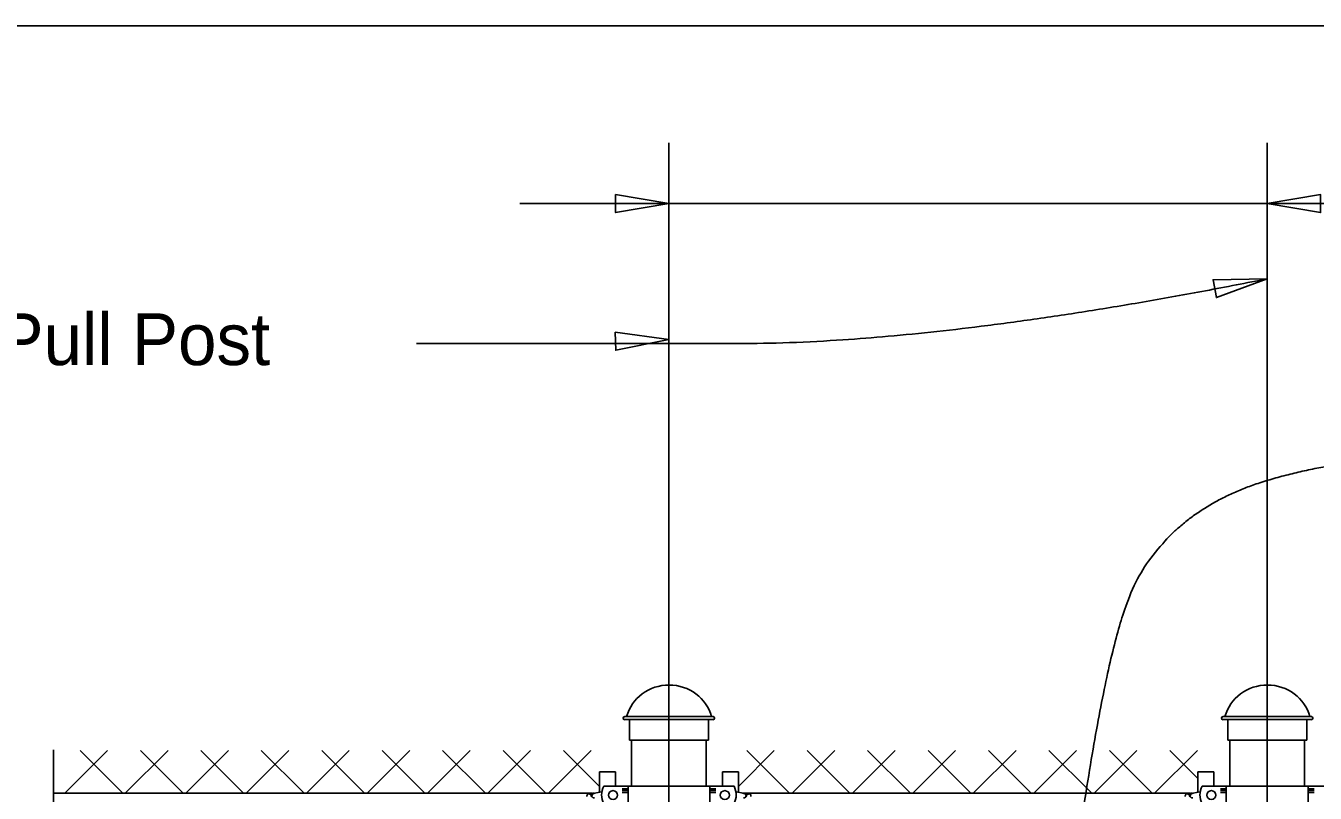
# Model space of a CAD drawing. Extents: x 0 to 72.1, y -7 to 30.
# Drawn here: x 23.75 to 28.78, y 25.02 to 28.01 of the extents above; entities that cross this region are included whole.
import ezdxf

# ---------------------------------------------------------------- set-up
doc = ezdxf.new("R2010")
doc.units = 0
for name, color, linetype in [('ActivePts-ConstElements', 7, 'Continuous'), ('AdhocPoint_dp', 7, 'Continuous'), ('Border', 7, 'Continuous'), ('PlotBorder_dp', 7, 'Continuous'), ('SheetBorder_dp', 7, 'Continuous'), ('TextStructures', 7, 'Continuous')]:
    doc.layers.add(name, color=color, linetype=linetype)

msp = doc.modelspace()

# ---------------------------------------------------------------- linework, layer by layer
at = {"layer": 'ActivePts-ConstElements'}
msp.add_lwpolyline([(0.016, 2.0538), (41.2266, 2.0538), (41.2266, 28.0138), (0.016, 28.0138)], close=True, dxfattribs=at)
at = {"layer": 'AdhocPoint_dp'}
for p, q in [((24.0698, 25.1899), (23.9031, 25.0233)), ((24.129, 25.0233), (23.9623, 25.1899)), ((24.3055, 25.1899), (24.1388, 25.0233)), ((24.3647, 25.0233), (24.198, 25.1899)), ((24.5412, 25.1899), (24.3745, 25.0233)), ((24.6004, 25.0233), (24.4337, 25.1899)), ((24.7769, 25.1899), (24.6102, 25.0233)), ((24.8361, 25.0233), (24.6694, 25.1899)), ((25.0126, 25.1899), (24.8459, 25.0233)), ((25.0718, 25.0233), (24.9051, 25.1899)), ((25.2483, 25.1899), (25.0816, 25.0233)), ((25.3075, 25.0233), (25.1408, 25.1899)), ((25.484, 25.1899), (25.3173, 25.0233)), ((25.5432, 25.0233), (25.3765, 25.1899)), ((25.7197, 25.1899), (25.553, 25.0233)), ((25.7789, 25.0233), (25.6122, 25.1899)), ((25.9554, 25.1899), (25.7887, 25.0233)), ((25.9881, 25.0498), (25.8479, 25.1899)), ((26.5298, 25.0498), (26.6699, 25.1899)), ((26.5625, 25.1899), (26.7291, 25.0233)), ((26.739, 25.0233), (26.9056, 25.1899)), ((26.7982, 25.1899), (26.9649, 25.0233)), ((26.9747, 25.0233), (27.1413, 25.1899)), ((27.0339, 25.1899), (27.2006, 25.0233)), ((27.2104, 25.0233), (27.377, 25.1899)), ((27.2696, 25.1899), (27.4363, 25.0233)), ((27.4461, 25.0233), (27.6127, 25.1899)), ((27.5053, 25.1899), (27.672, 25.0233)), ((27.6818, 25.0233), (27.8484, 25.1899)), ((27.741, 25.1899), (27.9077, 25.0233)), ((27.9175, 25.0233), (28.0841, 25.1899)), ((27.9767, 25.1899), (28.1434, 25.0233)), ((28.1532, 25.0233), (28.3198, 25.1899)), ((28.2124, 25.1899), (28.3214, 25.0809))]:
    msp.add_line(p, q, dxfattribs=at)
at = {"layer": 'Border'}
msp.add_line((25.6769, 27.321), (34.1393, 27.321), dxfattribs=at)
for points in [[(26.2589, 27.321), (26.0507, 27.3563), (26.0507, 27.2857)], [(28.5923, 27.321), (28.8005, 27.2857), (28.8005, 27.3563)], [(28.5923, 27.0276), (28.3811, 27.024), (28.394, 26.9547)], [(26.2589, 26.7908), (26.0497, 26.8198), (26.0518, 26.7492)]]:
    msp.add_lwpolyline(points, close=True, dxfattribs=at)
msp.add_lwpolyline([(23.8591, 25.192), (23.8591, 23.2357), (23.9625, 23.2357), (23.8591, 23.1907), (23.7558, 23.1457), (23.8591, 23.1457), (23.8591, 22.2521)], dxfattribs=at)
for points in [[(25.2748, 26.7753), (25.7285, 26.7753), (27.3249, 26.7753), (28.5923, 27.0276)], [(29.3872, 26.3263), (28.9587, 26.3515), (28.2277, 26.1329), (27.9253, 25.5441), (27.7572, 24.0372)]]:
    msp.add_open_spline(points, degree=2, dxfattribs=at)
at = {"layer": 'PlotBorder_dp'}
for p, q in [((26.0867, 25.3219), (26.4313, 25.3219)), ((26.4313, 25.3097), (26.0867, 25.3097)), ((26.1049, 25.2299), (26.1049, 25.3097)), ((26.413, 25.2299), (26.413, 25.3097)), ((28.42, 25.3219), (28.7646, 25.3219)), ((28.7646, 25.3097), (28.42, 25.3097)), ((28.4383, 25.2299), (28.4383, 25.3097)), ((28.7464, 25.2299), (28.7464, 25.3097)), ((26.413, 25.2299), (26.1049, 25.2299)), ((26.1131, 25.0504), (26.1131, 25.2299)), ((26.4048, 25.0504), (26.4048, 25.2299)), ((28.7464, 25.2299), (28.4383, 25.2299)), ((28.4465, 25.0504), (28.4465, 25.2299)), ((28.7381, 25.0504), (28.7381, 25.2299)), ((25.9881, 25.0264), (25.9881, 25.1066)), ((26.0506, 25.1066), (25.9881, 25.1066)), ((26.0506, 25.0504), (26.0506, 25.1066)), ((26.4673, 25.0504), (26.4673, 25.1066)), ((26.4673, 25.1066), (26.5298, 25.1066)), ((26.4673, 25.0504), (26.4673, 25.1066)), ((26.4673, 25.1066), (26.5298, 25.1066)), ((26.5298, 25.0264), (26.5298, 25.1066)), ((26.5298, 25.0264), (26.5298, 25.1066)), ((28.3214, 25.0264), (28.3214, 25.1066)), ((28.3839, 25.1066), (28.3214, 25.1066)), ((28.3839, 25.0504), (28.3839, 25.1066)), ((26.4148, 25.0504), (26.005, 25.0504)), ((26.0994, 24.9827), (26.0994, 25.0504)), ((26.1033, 25.0504), (26.5129, 25.0504)), ((26.4186, 24.9827), (26.4186, 25.0504)), ((28.7481, 25.0504), (28.3384, 25.0504)), ((28.4327, 24.9827), (28.4327, 25.0504)), ((28.4366, 25.0504), (28.8463, 25.0504)), ((28.7519, 24.9827), (28.7519, 25.0504)), ((25.9497, 25.0233), (23.8591, 25.0233)), ((25.9977, 25.0279), (25.9685, 25.0233)), ((26.0764, 25.0396), (26.0994, 25.0396)), ((26.0764, 25.0341), (26.0994, 25.0341)), ((26.0764, 25.026), (26.0994, 25.026)), ((26.4414, 25.0396), (26.4185, 25.0396)), ((26.4414, 25.0341), (26.4185, 25.0341)), ((26.4414, 25.026), (26.4185, 25.026)), ((26.5202, 25.0279), (26.5495, 25.0233)), ((26.5203, 25.0279), (26.5496, 25.0233)), ((26.5682, 25.0233), (28.283, 25.0233)), ((28.3311, 25.0279), (28.3018, 25.0233)), ((28.4098, 25.0396), (28.4327, 25.0396)), ((28.4098, 25.0341), (28.4327, 25.0341)), ((28.4098, 25.026), (28.4327, 25.026)), ((28.7748, 25.0396), (28.7518, 25.0396)), ((28.7748, 25.0341), (28.7518, 25.0341)), ((28.7748, 25.026), (28.7518, 25.026))]:
    msp.add_line(p, q, dxfattribs=at)
for centre, start, end in [((26.0868, 25.3156), 91.1647, 268.8353), ((26.4311, 25.3156), 271.1647, 88.8353), ((28.4201, 25.3156), 91.1647, 268.8353), ((28.7644, 25.3156), 271.1647, 88.8353)]:
    msp.add_arc(centre, 0.00613, start, end, dxfattribs=at)
for centre, major_axis, ratio, start_param, end_param in [((26.2596, 25.2808), (0.1711, 0), 0.957868, 0.252602, 2.888574), ((28.593, 25.2808), (0.1711, 0), 0.957868, 0.252602, 2.888574), ((26.0742, 25.0168), (-0.0776, 0), 0.957868, 5.81433, 6.762456), ((26.4436, 25.0168), (0.0776, 0), 0.957868, 5.803915, 6.752041), ((26.4436, 25.0168), (0.0776, 0), 0.957868, 5.803915, 6.752041), ((28.4076, 25.0168), (-0.0776, 0), 0.957868, 5.81433, 6.762456), ((25.9528, 25.01), (0.0142, 0), 0.957868, 1.486836, 3.141593), ((25.9576, 25.0155), (0.00872, 0), 0.957868, 1.29026, 2.959852), ((25.9641, 25.015), (0.00872, 0), 0.957868, 1.29026, 4.182385), ((25.9698, 25.0142), (-0.0115, -0.0041), 0.737732, 4.35367, 7.47816), ((26.5481, 25.0142), (0.0115, -0.0041), 0.737732, 5.08821, 8.212701), ((26.5481, 25.0142), (0.0115, -0.0041), 0.737732, 5.08821, 8.212701), ((26.5538, 25.015), (-0.00872, 0), 0.957868, 2.1008, 4.992926), ((26.5538, 25.015), (-0.00872, 0), 0.957868, 2.1008, 4.992926), ((26.5603, 25.0155), (-0.00872, 0), 0.957868, 3.323334, 4.992926), ((26.5603, 25.0155), (-0.00872, 0), 0.957868, 3.323334, 4.992926), ((26.565, 25.01), (-0.0142, 0), 0.957868, 3.141593, 4.79635), ((26.565, 25.01), (-0.0142, 0), 0.957868, 3.141593, 4.79635), ((28.2862, 25.01), (0.0142, 0), 0.957868, 1.486836, 3.141593), ((28.2909, 25.0155), (0.00872, 0), 0.957868, 1.29026, 2.959852), ((28.2974, 25.015), (0.00872, 0), 0.957868, 1.29026, 4.182385), ((28.3031, 25.0142), (-0.0115, -0.0041), 0.737732, 4.35367, 7.47816)]:
    msp.add_ellipse(centre, major_axis=major_axis, ratio=ratio, start_param=start_param, end_param=end_param, dxfattribs=at)
for centre, major_axis in [((26.0409, 25.0159), (0.0178, 0)), ((26.4769, 25.0159), (-0.0178, 0)), ((26.4769, 25.0159), (-0.0178, 0)), ((28.3743, 25.0159), (0.0178, 0))]:
    msp.add_ellipse(centre, major_axis=major_axis, ratio=0.957868, dxfattribs=at)
at = {"layer": 'SheetBorder_dp'}
for p, q in [((26.2589, 27.5581), (26.2589, 14.4491)), ((28.5923, 27.5581), (28.5923, 15.5577))]:
    msp.add_line(p, q, dxfattribs=at)

# ---------------------------------------------------------------- texts
at = {"layer": 'TextStructures'}
msp.add_text('℄ Pull Post', height=0.2016, dxfattribs=at).set_placement((23.4561, 26.6915))

doc.saveas('drawing.dxf')
